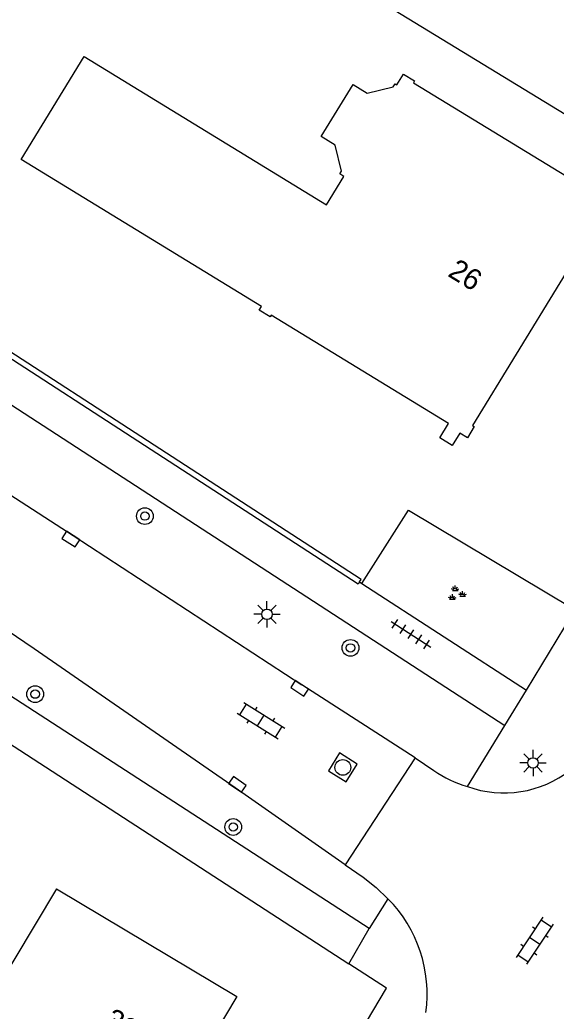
# Model space of a CAD drawing. Extents: x 136000 to 141014, y 402000 to 403500.
# Drawn here: x 137815.97 to 137841.55, y 402405.55 to 402452.83 of the extents above; entities that cross this region are included whole.
import ezdxf

# ---------------------------------------------------------------- set-up
doc = ezdxf.new("R2010")
doc.units = 0
for name, color, linetype in [('gg-afsc-erfafscheiding', 7, 'Continuous'), ('gg-afsc-hekwerk', 7, 'Continuous'), ('gg-afsc-muur', 7, 'Continuous'), ('gg-anno-huisnummerreeks BGT', 7, 'Continuous'), ('gg-bbg-gedigitaliseerde bebouwing', 7, 'Continuous'), ('gg-bbg-hoofdgebouw', 7, 'Continuous'), ('gg-bbg-luifel en loopbrug', 7, 'Continuous'), ('gg-knt-verharding', 7, 'Continuous'), ('gt-symb-boom', 7, 'Continuous'), ('gt-symb-groenvak', 7, 'Continuous'), ('gt-symb-klinker verharding', 7, 'Continuous'), ('gt-symb-kolk', 7, 'Continuous'), ('gt-symb-lichtmast', 7, 'Continuous'), ('gt-symb-rioolschacht', 7, 'Continuous'), ('gt-symb-tegel verharding', 7, 'Continuous')]:
    doc.layers.add(name, color=color, linetype=linetype)

# ---------------------------------------------------------------- blocks, each defined once
blk = doc.blocks.new('gt0-KOLK')
at = {"layer": 'gt-symb-kolk'}
blk.add_lwpolyline([(0, 0), (0.375, 0), (0.375, 0.4), (-0.375, 0.4), (-0.375, 0), (0, 0)], dxfattribs=at)
blk = doc.blocks.new('gt0-BOOM')
at = {"layer": 'gt-symb-boom'}
for radius in [0.4, 0.2]:
    blk.add_circle((0, 0), radius, dxfattribs=at)
blk = doc.blocks.new('gt0-TEG1')
at = {"layer": 'gt-symb-tegel verharding'}
for p, q in [((-1.125, 0), (1.125, 0)), ((-0.9, -0.25), (-0.9, 0.25)), ((-0.45, -0.25), (-0.45, 0.25)), ((0, -0.25), (0, 0.25)), ((0.45, -0.25), (0.45, 0.25)), ((0.9, -0.25), (0.9, 0.25))]:
    blk.add_line(p, q, dxfattribs=at)
blk = doc.blocks.new('gt0-LMAST')
at = {"layer": 'gt-symb-lichtmast'}
for p, q in [((-0.005, 0.246), (-0.005, 0.621)), ((-0.182, 0.173), (-0.447, 0.438)), ((0.172, 0.173), (0.437, 0.438)), ((-0.255, -0.004), (-0.63, -0.004)), ((-0.182, -0.181), (-0.447, -0.446)), ((-0.005, -0.254), (-0.005, -0.629)), ((0.437, -0.446), (0.172, -0.181)), ((0.245, -0.004), (0.62, -0.004))]:
    blk.add_line(p, q, dxfattribs=at)
blk.add_circle((-0.005, -0.004), 0.25, dxfattribs=at)
blk = doc.blocks.new('gt0-GRVAK')
at = {"layer": 'gt-symb-groenvak'}
for p, q in [((-0.11, 0.189), (-0.228, 0.24)), ((-0.182, 0.153), (0.088, 0.153)), ((-0.091, 0.211), (-0.156, 0.322)), ((-0.047, 0.214), (-0.047, 0.393)), ((-0.004, 0.211), (0.061, 0.322)), ((0.015, 0.189), (0.133, 0.24)), ((0.262, -0.052), (0.197, 0.059)), ((0.305, -0.049), (0.305, 0.13)), ((0.349, -0.052), (0.414, 0.059)), ((-0.245, -0.228), (-0.363, -0.177)), ((-0.318, -0.264), (-0.047, -0.264)), ((-0.226, -0.206), (-0.291, -0.095)), ((-0.183, -0.203), (-0.183, -0.024)), ((-0.139, -0.206), (-0.074, -0.095)), ((-0.12, -0.228), (-0.002, -0.177)), ((0.243, -0.074), (0.125, -0.023)), ((0.17, -0.11), (0.441, -0.11)), ((0.368, -0.074), (0.486, -0.023))]:
    blk.add_line(p, q, dxfattribs=at)
blk = doc.blocks.new('gt0-RS')
at = {"layer": 'gt-symb-rioolschacht'}
blk.add_lwpolyline([(-0.5, -0.5), (0.5, -0.5), (0.5, 0.5), (-0.5, 0.5)], close=True, dxfattribs=at)
blk.add_circle((0, 0), 0.375, dxfattribs=at)
blk = doc.blocks.new('gt0-KL1')
at = {"layer": 'gt-symb-klinker verharding'}
for p, q in [((-1.15, 0.3), (1.15, 0.3)), ((-1, -0.3), (-1, 0.3)), ((-0.5, 0.3), (-0.5, 0.45)), ((0, -0.3), (0, 0.3)), ((0.5, 0.3), (0.5, 0.45)), ((1, -0.3), (1, 0.3)), ((-1.15, -0.3), (1.15, -0.3)), ((-0.5, -0.45), (-0.5, -0.3)), ((0.5, -0.45), (0.5, -0.3))]:
    blk.add_line(p, q, dxfattribs=at)

msp = doc.modelspace()

# ---------------------------------------------------------------- linework, layer by layer
at = {"layer": 'gg-afsc-erfafscheiding'}
msp.add_line((137815.069, 402418.58), (137831.664, 402407.813), dxfattribs=at)
at = {"layer": 'gg-afsc-hekwerk'}
msp.add_line((137834.504, 402429.436), (137842.335, 402424.776), dxfattribs=at)
at = {"layer": 'gg-afsc-muur'}
msp.add_line((137832.29, 402425.947), (137834.504, 402429.436), dxfattribs=at)
for points in [[(137832.176, 402426.021), (137832.25, 402426.134), (137804.654, 402444.035), (137804.583, 402443.926)], [(137832.176, 402426.021), (137832.108, 402425.916), (137804.512, 402443.817)]]:
    msp.add_lwpolyline(points, dxfattribs=at)
at = {"layer": 'gg-bbg-gedigitaliseerde bebouwing'}
msp.add_lwpolyline([(137817.72, 402411.38), (137813.633, 402404.575), (137813.983, 402404.364)], dxfattribs=at)
at = {"layer": 'gg-bbg-hoofdgebouw'}
for points in [[(137816.036, 402446.172), (137819.044, 402451.085), (137830.6, 402444.01), (137831.425, 402445.357), (137831.229, 402445.477), (137831.307, 402445.605), (137831.015, 402446.851), (137830.349, 402447.259), (137831.869, 402449.74), (137832.534, 402449.333), (137833.78, 402449.626), (137833.874, 402449.779), (137833.959, 402449.727), (137834.273, 402450.239), (137834.801, 402449.915), (137834.749, 402449.83), (137843.627, 402444.394)], [(137843.799, 402443.679), (137837.555, 402433.479), (137837.64, 402433.427), (137837.316, 402432.898), (137836.958, 402433.117), (137836.592, 402432.52), (137835.995, 402432.886), (137836.413, 402433.568), (137827.961, 402438.742), (137827.909, 402438.657), (137827.38, 402438.981), (137827.49, 402439.16), (137816.036, 402446.172)], [(137817.72, 402411.38), (137826.32, 402406.25), (137822.23, 402399.39)]]:
    msp.add_lwpolyline(points, dxfattribs=at)
at = {"layer": 'gg-bbg-luifel en loopbrug'}
msp.add_line((137832.352, 402454.205), (137849.003, 402444.044), dxfattribs=at)
at = {"layer": 'gg-knt-verharding'}
for p, q in [((137803.665, 402442.195), (137839.104, 402419.181)), ((137832.628, 402409.486), (137805.551, 402427.049)), ((137832.176, 402426.021), (137832.29, 402425.947)), ((137832.29, 402425.947), (137840.132, 402420.858)), ((137834.831, 402417.625), (137829.425, 402421.109)), ((137839.104, 402419.181), (137840.132, 402420.858)), ((137837.315, 402416.263), (137839.104, 402419.181)), ((137834.831, 402417.625), (137831.48, 402412.533)), ((137834.831, 402417.625), (137835.714, 402417.028)), ((137831.48, 402412.533), (137826.238, 402416.201)), ((137833.527, 402410.911), (137832.628, 402409.486)), ((137831.664, 402407.813), (137832.628, 402409.486))]:
    msp.add_line(p, q, dxfattribs=at)
for points in [[(137803.679, 402437.835), (137818.514, 402428.231), (137829.425, 402421.109)], [(137826.238, 402416.201), (137816.66, 402422.834), (137815.377, 402423.702), (137807.904, 402428.595)], [(137840.132, 402420.858), (137842.689, 402425.086), (137842.568, 402425.16)], [(137831.48, 402412.533), (137832.343, 402411.934), (137832.96, 402411.451), (137833.527, 402410.911)], [(137826.403, 402394.379), (137826.232, 402394.477), (137833.463, 402406.646), (137831.664, 402407.813)]]:
    msp.add_lwpolyline(points, dxfattribs=at)
for centre, radius, start, end in [((137838.833, 402421.498), 5.451, 235.0936, 253.827), ((137839.064, 402421.095), 5.138, 250.1047, 307.9712), ((137828.972, 402406.381), 6.424, 351.9244, 44.8378)]:
    msp.add_arc(centre, radius, start, end, dxfattribs=at)

# ---------------------------------------------------------------- block references
at = {"layer": 'gt-symb-boom'}
for p in [(137821.938, 402429.16), (137831.742, 402422.873), (137816.704, 402420.669), (137826.15, 402414.332)]:
    msp.add_blockref('gt0-BOOM', p, dxfattribs=at)
at = {"layer": 'gt-symb-groenvak'}
msp.add_blockref('gt0-GRVAK', (137836.781, 402425.457), dxfattribs=at)
at = {"layer": 'gt-symb-klinker verharding'}
for p, rotation in [((137827.473, 402419.408), -32.00538320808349), ((137840.523, 402408.907), -123.70595653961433)]:
    msp.add_blockref('gt0-KL1', p, dxfattribs=dict(at, rotation=rotation))
at = {"layer": 'gt-symb-kolk'}
for p, rotation in [((137818.514, 402428.231), 147.04099012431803), ((137829.425, 402421.109), 146.83440068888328), ((137826.238, 402416.201), -34.6915288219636)]:
    msp.add_blockref('gt0-KOLK', p, dxfattribs=dict(at, rotation=rotation))
at = {"layer": 'gt-symb-lichtmast'}
for p in [(137827.765, 402424.48), (137840.451, 402417.392)]:
    msp.add_blockref('gt0-LMAST', p, dxfattribs=at)
at = {"layer": 'gt-symb-rioolschacht', "rotation": -32.211897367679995}
msp.add_blockref('gt0-RS', (137831.377, 402417.174), dxfattribs=at)
at = {"layer": 'gt-symb-tegel verharding', "rotation": -33.08630739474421}
msp.add_blockref('gt0-TEG1', (137834.623, 402423.527), dxfattribs=at)

# ---------------------------------------------------------------- texts
at = {"layer": 'gg-anno-huisnummerreeks BGT'}
for s, rotation, p in [('26', 328.5, (137836.333, 402440.632)), ('32', 329.2, (137819.943, 402404.882))]:
    msp.add_text(s, height=1, rotation=rotation, dxfattribs=at).set_placement(p)

doc.saveas('drawing.dxf')
